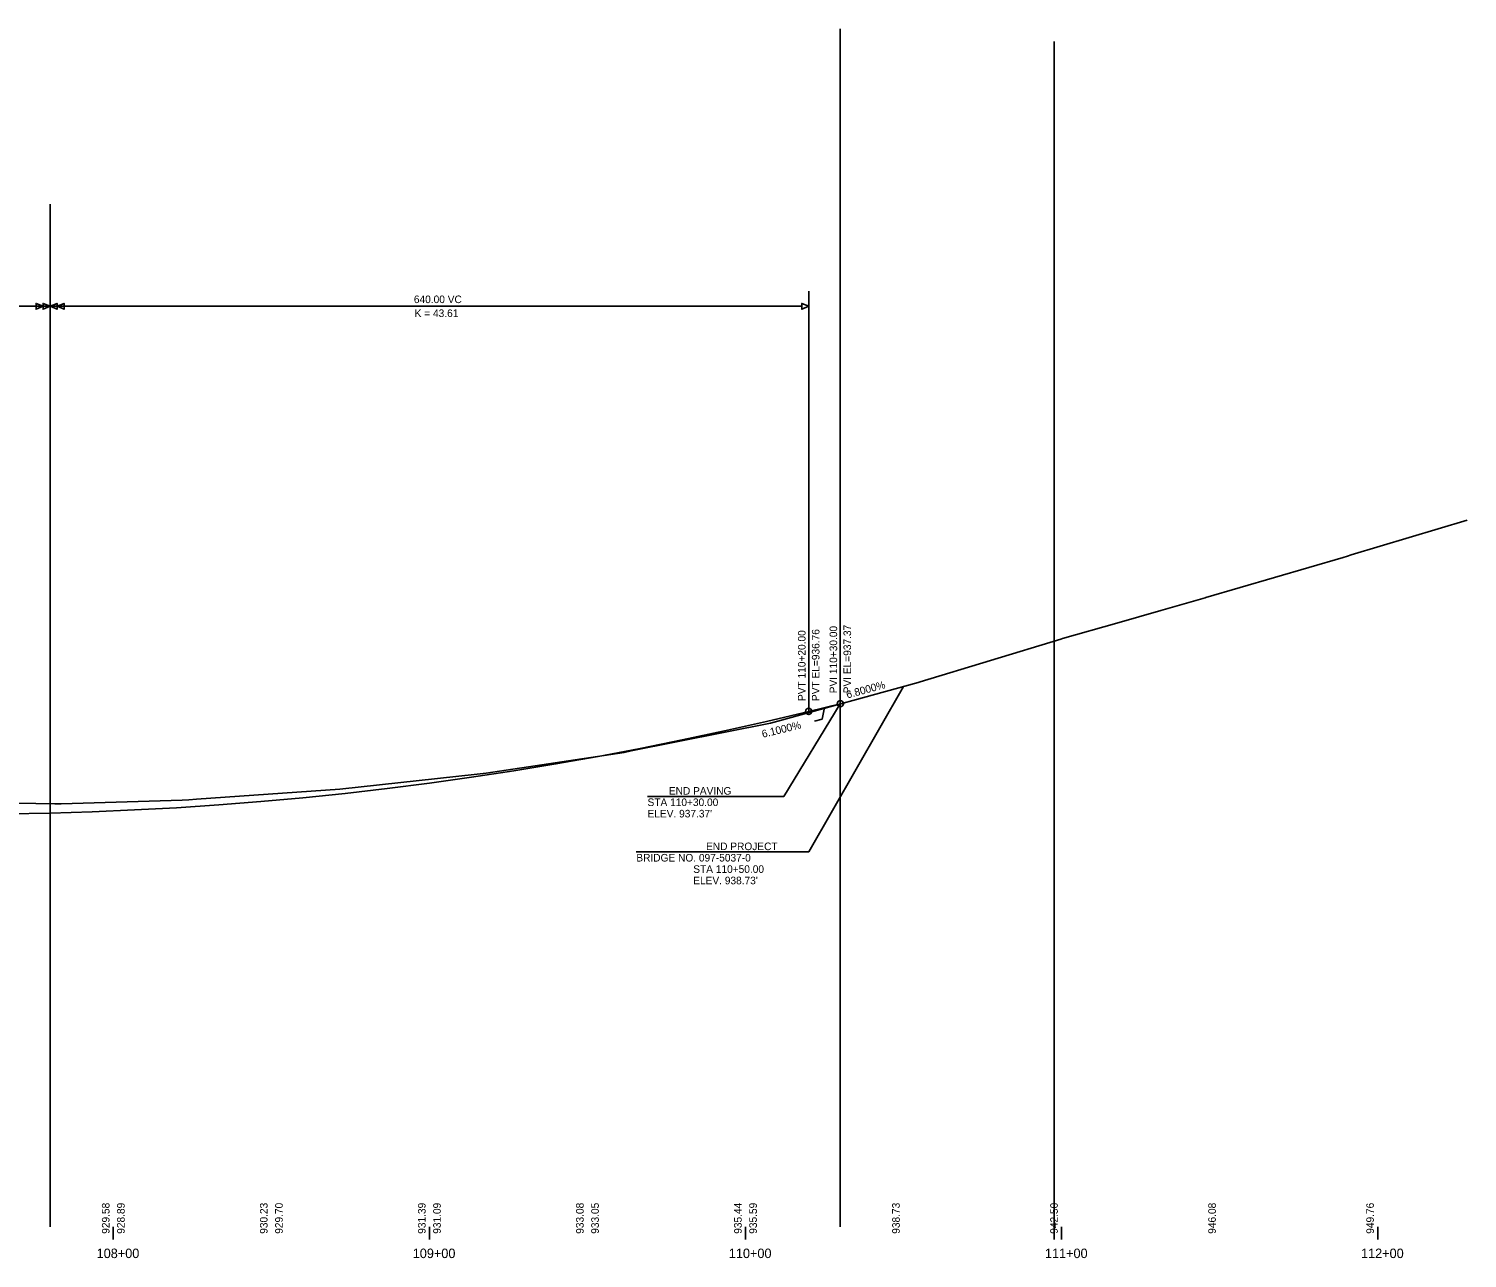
# Model space of a CAD drawing. Extents: x 2091593 to 2093109, y 1330214 to 1331965.
# Drawn here: x 2092372.9 to 2092828, y 1331544.3 to 1331933.2 of the extents above; entities that cross this region are included whole.
import ezdxf

# ---------------------------------------------------------------- set-up
doc = ezdxf.new("R2010")
doc.units = 0
for name, color, linetype in [('ATMS_P_ITS-Device-and-Conduit', 7, 'Continuous'), ('ATMS_P_Utility-Pole', 7, 'Continuous'), ('PROF_E_Ground-Line', 7, 'Continuous'), ('PROF_E_Ground-Text', 7, 'Continuous'), ('PROF_P_CONSTCL-Cell', 7, 'Continuous'), ('PROF_P_CONSTCL-Line', 7, 'Continuous'), ('PROF_P_Finish-Elev-Text', 7, 'Continuous'), ('PROF_P_Finish-Text', 7, 'Continuous'), ('SHT_B_Grid-Station-Text', 7, 'Continuous'), ('SHT_B_Major-Station-Tic-Line', 7, 'Continuous')]:
    doc.layers.add(name, color=color, linetype=linetype)

msp = doc.modelspace()

# ---------------------------------------------------------------- linework, layer by layer
at = {"layer": 'ATMS_P_ITS-Device-and-Conduit'}
for p, q in [((2092629.69, 1331554.21), (2092629.69, 1331933.2)), ((2092697.29, 1331550.21), (2092697.29, 1331929.2))]:
    msp.add_line(p, q, dxfattribs=at)
at = {"layer": 'ATMS_P_Utility-Pole'}
msp.add_line((2092379.69, 1331554.21), (2092379.69, 1331877.71), dxfattribs=at)
at = {"layer": 'PROF_E_Ground-Line'}
msp.add_lwpolyline([(2092339.3, 1331688.72), (2092381.17, 1331688.01), (2092383.21, 1331688.01), (2092421.43, 1331689.19), (2092423.55, 1331689.26), (2092426.05, 1331689.45), (2092471.37, 1331692.67), (2092514.82, 1331697.43), (2092517.7, 1331697.71), (2092559.22, 1331703.98), (2092561.32, 1331704.28), (2092563.51, 1331704.74), (2092607.61, 1331713.53), (2092609.87, 1331714.16), (2092654.35, 1331726.4), (2092654.91, 1331726.57), (2092699.43, 1331740.12), (2092699.98, 1331740.27), (2092717.16, 1331745.19), (2092731.07, 1331749.16), (2092745.11, 1331753.17), (2092745.36, 1331753.24), (2092788.73, 1331765.96), (2092790.09, 1331766.37), (2092791.25, 1331766.73), (2092828.02, 1331777.74)], dxfattribs=at)
at = {"layer": 'PROF_P_CONSTCL-Cell'}
for centre in [(2092619.69, 1331717.25), (2092629.69, 1331719.69)]:
    msp.add_circle(centre, 1, dxfattribs=at)
at = {"layer": 'PROF_P_CONSTCL-Line'}
msp.add_line((2092619.69, 1331717.25), (2092629.69, 1331719.69), dxfattribs=at)
msp.add_lwpolyline([(2092366.36, 1331684.86), (2092379.69, 1331685.1), (2092393.03, 1331685.5), (2092406.36, 1331686.06), (2092419.69, 1331686.79), (2092433.03, 1331687.68), (2092446.36, 1331688.73), (2092459.69, 1331689.95), (2092473.03, 1331691.32), (2092486.36, 1331692.86), (2092499.69, 1331694.57), (2092513.03, 1331696.44), (2092526.36, 1331698.47), (2092539.69, 1331700.66), (2092553.03, 1331703.02), (2092566.36, 1331705.54), (2092579.69, 1331708.22), (2092593.03, 1331711.06), (2092606.36, 1331714.07), (2092619.69, 1331717.25)], dxfattribs=at)
at = {"layer": 'PROF_P_Finish-Text'}
for p, q in [((2092619.69, 1331717.25), (2092619.69, 1331850.21)), ((2092619.69, 1331717.25), (2092619.69, 1331767.25)), ((2092629.69, 1331719.69), (2092629.69, 1331769.69)), ((2092623.95, 1331714.83), (2092624.69, 1331718.47)), ((2092621.47, 1331714.12), (2092623.95, 1331714.83))]:
    msp.add_line(p, q, dxfattribs=at)
for points in [[(2091981.91, 1331845.41), (2092617.48, 1331845.41)], [(2092565.1, 1331672.84), (2092619.69, 1331672.84), (2092649.69, 1331725.12)], [(2092568.64, 1331690.28), (2092611.81, 1331690.28), (2092629.69, 1331719.69)]]:
    msp.add_lwpolyline(points, dxfattribs=at)
for points in [[(2092377.48, 1331845.41), (2092375.26, 1331846.32), (2092375.26, 1331844.49)], [(2092379.69, 1331845.41), (2092377.48, 1331846.32), (2092377.48, 1331844.49)], [(2092379.69, 1331845.41), (2092381.91, 1331846.32), (2092381.91, 1331844.49)], [(2092381.91, 1331845.41), (2092384.13, 1331846.32), (2092384.13, 1331844.49)], [(2092619.69, 1331845.41), (2092617.48, 1331846.32), (2092617.48, 1331844.49)]]:
    msp.add_lwpolyline(points, close=True, dxfattribs=at)
at = {"layer": 'SHT_B_Major-Station-Tic-Line'}
for p, q in [((2092399.69, 1331550.21), (2092399.69, 1331554.21)), ((2092499.69, 1331550.21), (2092499.69, 1331554.21)), ((2092599.69, 1331550.21), (2092599.69, 1331554.21)), ((2092699.69, 1331550.21), (2092699.69, 1331554.21)), ((2092799.69, 1331550.21), (2092799.69, 1331554.21))]:
    msp.add_line(p, q, dxfattribs=at)

# ---------------------------------------------------------------- texts
at = {"layer": 'PROF_E_Ground-Text'}
for s, p in [('  929.58', (2092398.49, 1331550.21)), ('  930.23', (2092448.49, 1331550.21)), ('  931.39', (2092498.49, 1331550.21)), ('  933.08', (2092548.49, 1331550.21)), ('  935.44', (2092598.49, 1331550.21)), ('  938.73', (2092648.49, 1331550.21)), ('  942.50', (2092698.49, 1331550.21)), ('  946.08', (2092748.49, 1331550.21)), ('  949.76', (2092798.49, 1331550.21))]:
    msp.add_text(s, height=2.4, rotation=90, dxfattribs=at).set_placement(p)
at = {"layer": 'PROF_P_Finish-Elev-Text'}
for s, p in [('  928.89', (2092403.29, 1331550.21)), ('  929.70', (2092453.29, 1331550.21)), ('  931.09', (2092503.29, 1331550.21)), ('  933.05', (2092553.29, 1331550.21)), ('  935.59', (2092603.29, 1331550.21))]:
    msp.add_text(s, height=2.4, rotation=90, dxfattribs=at).set_placement(p)
at = {"layer": 'PROF_P_Finish-Text'}
for s, p in [('640.00 VC', (2092494.78, 1331846.41)), ('K = 43.61', (2092495.03, 1331842.01))]:
    msp.add_text(s, height=2.4, dxfattribs=at).set_placement(p)
for s, height, rotation, p in [('  PVI 110+30.00', 2.4, 90, (2092628.69, 1331721.19)), ('  PVI EL=937.37', 2.4, 90, (2092633.09, 1331721.19)), ('  PVT 110+20.00', 2.4, 90, (2092618.69, 1331718.75)), ('  PVT EL=936.76', 2.4, 90, (2092623.09, 1331718.75)), ('6.8000%', 2.4, 15.2163, (2092631.91, 1331721.32)), ('6.1000%', 2.4, 13.7122, (2092605.16, 1331708.89)), ('STA 110+30.00', 2.3994, 359.9936, (2092568.7, 1331687.31)), ('END PAVING', 2.399, 359.9936, (2092575.45, 1331690.91)), ("ELEV. 937.37'", 2.3994, 359.9936, (2092568.7, 1331683.71)), ('END PROJECT', 2.3994, 360, (2092587.21, 1331673.36)), ('BRIDGE NO. 097-5037-0', 2.3994, 360, (2092565.16, 1331669.76)), ('STA 110+50.00', 2.3994, 360, (2092583.16, 1331666.16)), ("ELEV. 938.73'", 2.3994, 360, (2092583.16, 1331662.56))]:
    msp.add_text(s, height=height, rotation=rotation, dxfattribs=at).set_placement(p)
at = {"layer": 'SHT_B_Grid-Station-Text'}
for s, p in [('108+00', (2092394.42, 1331544.31)), ('109+00', (2092494.42, 1331544.31)), ('110+00', (2092594.42, 1331544.31)), ('111+00', (2092694.42, 1331544.31)), ('112+00', (2092794.42, 1331544.31))]:
    msp.add_text(s, height=3, dxfattribs=at).set_placement(p)

doc.saveas('drawing.dxf')
